AutomationDirect Productivity Suite project: GS30_ModbusRTU (software 4.2.0 (39))
author: Test
Rung notation: left to right = series (deeper-indented lines continue the line above), [a | b] = parallel branches, -- = plain wire, BOX.Pin = further input of the box above; 'quoted' = tag name, ? = field left empty; instruction and field names as stored in the project; options that are off are not listed.

HARDWARE
  Base 1 (1 slots)
    slot 0: P1-550

STRUCTURES
STRUCTURE GS30_Status
  Fault_Code : Uint8, strLength=15
  Warning_Code : Uint8, strLength=15
  Stop : Boolean, strLength=15
  Decel_During_Stop : Boolean, strLength=15
  Standby : Boolean, strLength=15
  Run : Boolean, strLength=15
  JOG_Active : Boolean, strLength=15
  Forward : Boolean, strLength=15
  Transition_Rev_To_FWD : Boolean, strLength=15
  Transition_FWD_To_REV : Boolean, strLength=15
  Reverse : Boolean, strLength=15
  Main_Freq_From_Comm_Interface : Boolean, strLength=15
  Main_Freq_From_Analog : Boolean, strLength=15
  CMD_Operated_By_Comm_Interface : Boolean, strLength=15
  Params_Have_Been_Locked : Boolean, strLength=15
  Drive_Stopped : Boolean, strLength=15
  Drive_Running : Boolean, strLength=15
  Frequency_Command : Int16, strLength=15
  Output_Frequency : Int16, strLength=15
  Output_Current : Int16, strLength=15
  DC_Bus_Voltage : Int16, strLength=15
  Output_Voltage : Int16, strLength=15
  MultiSpeed_Or_PID_Input_StepNo : Int16, strLength=15
  Max_Output_Torque_N-m : Int16, strLength=15
  Digital_Input_Counter_Value : Int16, strLength=15
  Power_Factor_Angle : Int16, strLength=15
  Output_Torque : Int16, strLength=15
  Actual_Motor_Speed_RPM : Int16, strLength=15
  PG1_Feedback_Count : Int16, strLength=15
  PG2_Pulse_Count : Int16, strLength=15
  Power_Output_kW : Int16, strLength=15
STRUCTURE GS30_Command
  Stop : Boolean, strLength=15
  Run_Forward : Boolean, strLength=15
  Run_Reverse : Boolean, strLength=15
  JOG_Forward : Boolean, strLength=15
  JOG_Reverse : Boolean, strLength=15
  Frequency_Command : Uint16, strLength=15
  JOG_Frequency : Array of Uint16, dimensions=1, strLength=15

TAGS  (name : type @system ID = initial value)
  GS30_Modbus_Read : Array[16] of Uint16 @AR1US16-000004
  GS30_Modbus_Write : Array[3] of Int16 @AR1S16-000002
  GS30_ExtendedStatus : Array[8] of Uint16 @AR1US16-000001
  GS30_Status : GS30_Status @USTRUC-000001
  ExpDataInput : Array[6] of Uint8 @AR1US8-000001
  ExpDataInput2 : Array[1] of Uint16 @AR1US16-000003
  'Exp Set' : Boolean @C-000062
  'Exp Get' : Boolean @C-000073
  Enable_GS30_Com : Boolean @C-000079
  TwoBytes : Array[2] of Uint8 @AR1US8-000002
  GS30_IP_Address : String(15) @STR-000024
  GS30_Command : GS30_Command @USTRUC-000003
  Blank_IP : Boolean @C-000085
  GS30_IP_Address_Length : Uint16 @US16-000004

SYSTEM TAGS USED OR MAPPED TO MODBUS
  GS_MBRead : MRX @SSTRUC-000006  // System Structure for Modbus Read
  GS_MBWrite : MWX @SSTRUC-000007  // System Structure for Modbus Write

TASK Main  (Run Every Scan)
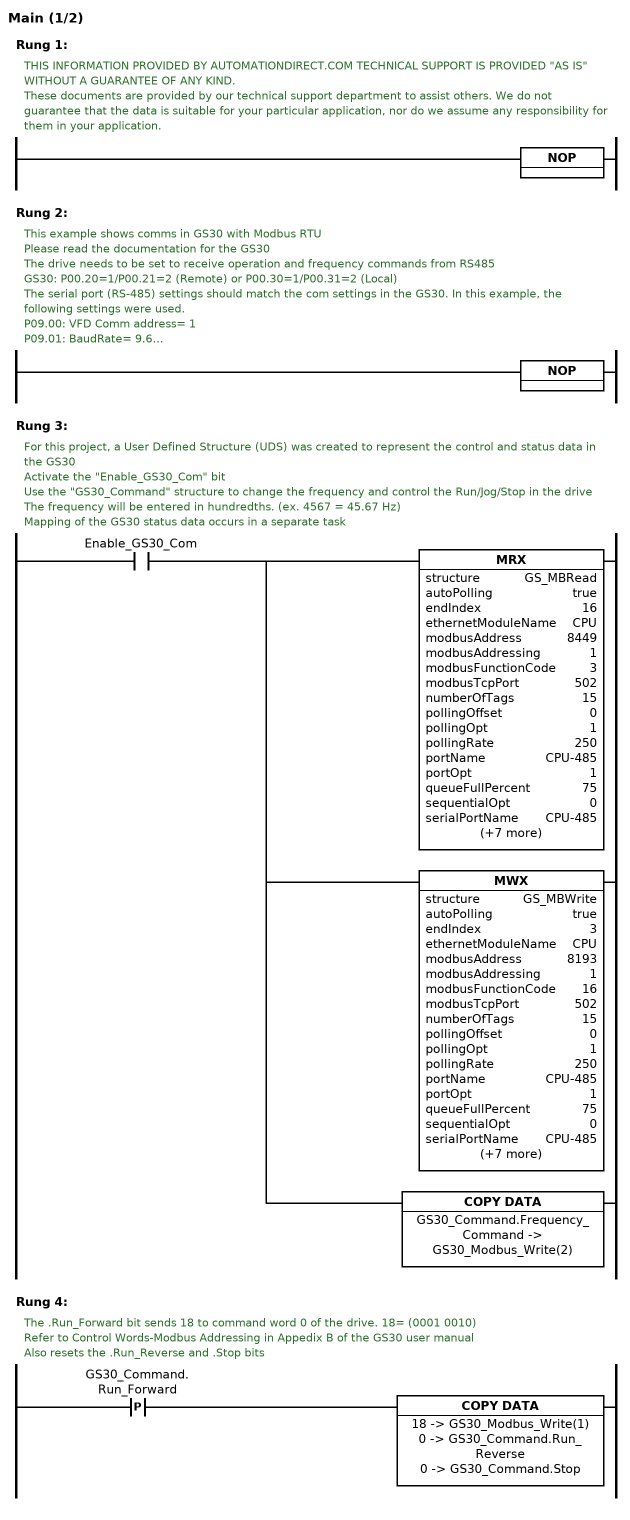
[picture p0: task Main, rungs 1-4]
Rung 1:
  // THIS INFORMATION PROVIDED BY AUTOMATIONDIRECT.COM TECHNICAL SUPPORT IS PROVIDED "AS IS" WITHOUT A GUARANTEE OF ANY KIND.
  // These documents are provided by our technical support department to assist others. We do not guarantee that the data is suitable for your particular application, nor do we assume any responsibility for them in your application.
  NOP()
Rung 2:
  // This example shows comms in GS30 with Modbus RTU
  // Please read the documentation for the GS30
  // The drive needs to be set to receive operation and frequency commands from RS485
  // GS30: P00.20=1/P00.21=2 (Remote) or P00.30=1/P00.31=2 (Local)
  // The serial port (RS-485) settings should match the com settings in the GS30. In this example, the following settings were used.
  // P09.00: VFD Comm address= 1
  // P09.01: BaudRate= 9.6k
  // P09.04: Modbus Protocol= 12: (8 data bits, No parity, 1 stop bit) for RTU
  NOP()
Rung 3:
  // For this project, a User Defined Structure (UDS) was created to represent the control and status data in the GS30
  // Activate the "Enable_GS30_Com" bit
  // Use the "GS30_Command" structure to change the frequency and control the Run/Jog/Stop in the drive
  // The frequency will be entered in hundredths. (ex. 4567 = 45.67 Hz)
  // Mapping of the GS30 status data occurs in a separate task
  NO(Enable_GS30_Com)
    [ MRX(structure=GS_MBRead, autoPolling, endIndex=16, ethernetModuleName=CPU, modbusAddress=8449, modbusAddressing=1, modbusFunctionCode=3, modbusTcpPort=502, numberOfTags=15, pollingOffset=0, pollingOpt=1, pollingRate=250, portName=CPU-485, portOpt=1, queueFullPercent=75, sequentialOpt=0, serialPortName=CPU-485, slaveEthernetNodeNum=255, slaveIpAddress=192.168.1.6, slaveSerialNodeNum=1, startTag=GS30_Modbus_Read, startingIndex=1, stringLength=2, wordSwap)
    | MWX(structure=GS_MBWrite, autoPolling, endIndex=3, ethernetModuleName=CPU, modbusAddress=8193, modbusAddressing=1, modbusFunctionCode=16, modbusTcpPort=502, numberOfTags=15, pollingOffset=0, pollingOpt=1, pollingRate=250, portName=CPU-485, portOpt=1, queueFullPercent=75, sequentialOpt=0, serialPortName=CPU-485, slaveEthernetNodeNum=255, slaveIpAddress=192.168.1.6, slaveSerialNodeNum=1, startTag=GS30_Modbus_Write, startingIndex=1, stringLength=2, wordSwap)
    | CPY(GS30_Command.Frequency_Command -> GS30_Modbus_Write(2)) ]
Rung 4:
  // The .Run_Forward bit sends 18 to command word 0 of the drive. 18= (0001 0010)
  // Refer to Control Words-Modbus Addressing in Appedix B of the GS30 user manual
  // Also resets the .Run_Reverse and .Stop bits
  NOE(GS30_Command.Run_Forward, rising)
    CPY(18 -> GS30_Modbus_Write(1), 0 -> GS30_Command.Run_Reverse, 0 -> GS30_Command.Stop)
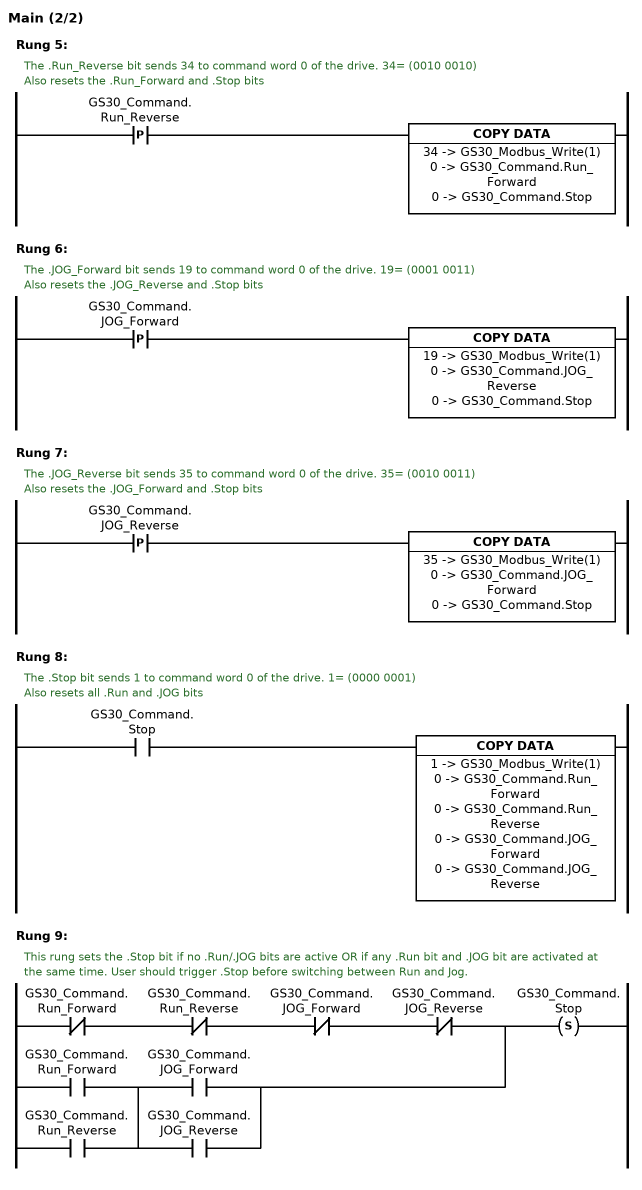
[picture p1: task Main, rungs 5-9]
Rung 5:
  // The .Run_Reverse bit sends 34 to command word 0 of the drive. 34= (0010 0010)
  // Also resets the .Run_Forward and .Stop bits
  NOE(GS30_Command.Run_Reverse, rising)
    CPY(34 -> GS30_Modbus_Write(1), 0 -> GS30_Command.Run_Forward, 0 -> GS30_Command.Stop)
Rung 6:
  // The .JOG_Forward bit sends 19 to command word 0 of the drive. 19= (0001 0011)
  // Also resets the .JOG_Reverse and .Stop bits
  NOE(GS30_Command.JOG_Forward, rising)
    CPY(19 -> GS30_Modbus_Write(1), 0 -> GS30_Command.JOG_Reverse, 0 -> GS30_Command.Stop)
Rung 7:
  // The .JOG_Reverse bit sends 35 to command word 0 of the drive. 35= (0010 0011)
  // Also resets the .JOG_Forward and .Stop bits
  NOE(GS30_Command.JOG_Reverse, rising)
    CPY(35 -> GS30_Modbus_Write(1), 0 -> GS30_Command.JOG_Forward, 0 -> GS30_Command.Stop)
Rung 8:
  // The .Stop bit sends 1 to command word 0 of the drive. 1= (0000 0001)
  // Also resets all .Run and .JOG bits
  NO(GS30_Command.Stop)
    CPY(1 -> GS30_Modbus_Write(1), 0 -> GS30_Command.Run_Forward, 0 -> GS30_Command.Run_Reverse, 0 -> GS30_Command.JOG_Forward, 0 -> GS30_Command.JOG_Reverse)
Rung 9:
  // This rung sets the .Stop bit if no .Run/.JOG bits are active OR if any .Run bit and .JOG bit are activated at the same time. User should trigger .Stop before switching between Run and Jog.
  [ NC(GS30_Command.Run_Forward) NC(GS30_Command.Run_Reverse) NC(GS30_Command.JOG_Forward)
      NC(GS30_Command.JOG_Reverse)
    | [NO(GS30_Command.Run_Forward) | NO(GS30_Command.Run_Reverse)]
      [NO(GS30_Command.JOG_Forward) | NO(GS30_Command.JOG_Reverse)] ]
    SET(GS30_Command.Stop)

TASK GS30_Status_Mapping  (Run Every Scan)
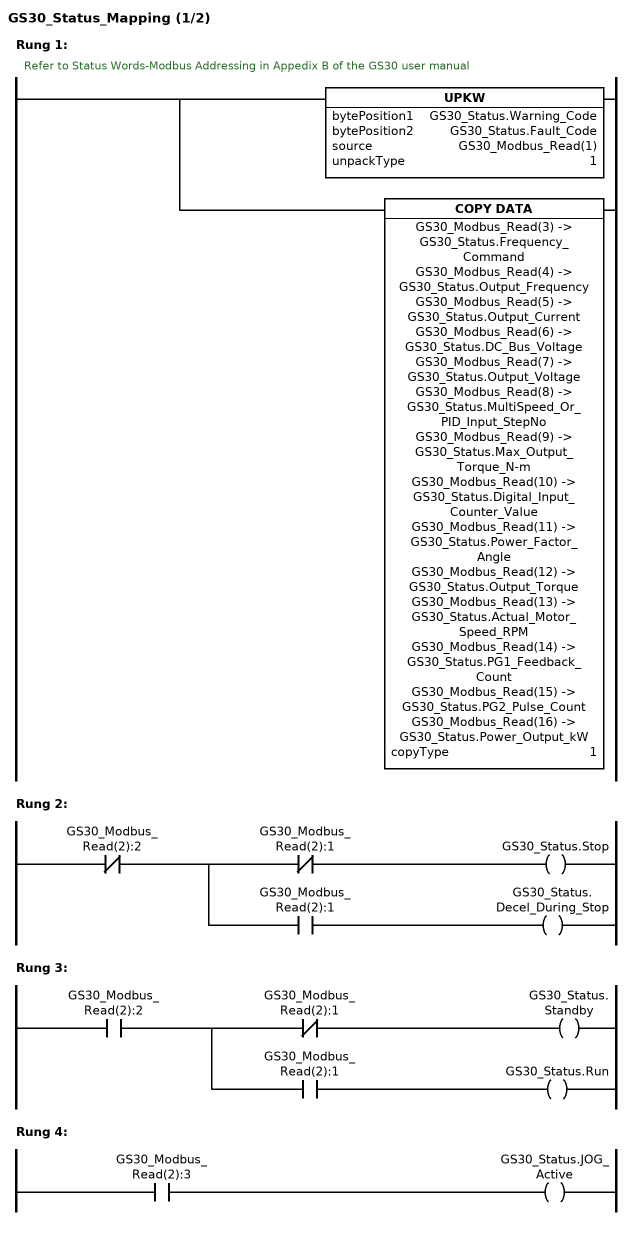
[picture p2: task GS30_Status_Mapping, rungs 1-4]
Rung 1:
  // Refer to Status Words-Modbus Addressing in Appedix B of the GS30 user manual
  UPKW(bytePosition1=GS30_Status.Warning_Code, bytePosition2=GS30_Status.Fault_Code, source=GS30_Modbus_Read(1), unpackType=1)
  CPY(GS30_Modbus_Read(3) -> GS30_Status.Frequency_Command, GS30_Modbus_Read(4) -> GS30_Status.Output_Frequency, GS30_Modbus_Read(5) -> GS30_Status.Output_Current, GS30_Modbus_Read(6) -> GS30_Status.DC_Bus_Voltage, GS30_Modbus_Read(7) -> GS30_Status.Output_Voltage, GS30_Modbus_Read(8) -> GS30_Status.MultiSpeed_Or_PID_Input_StepNo, GS30_Modbus_Read(9) -> GS30_Status.Max_Output_Torque_N-m, GS30_Modbus_Read(10) -> GS30_Status.Digital_Input_Counter_Value, GS30_Modbus_Read(11) -> GS30_Status.Power_Factor_Angle, GS30_Modbus_Read(12) -> GS30_Status.Output_Torque, GS30_Modbus_Read(13) -> GS30_Status.Actual_Motor_Speed_RPM, GS30_Modbus_Read(14) -> GS30_Status.PG1_Feedback_Count, GS30_Modbus_Read(15) -> GS30_Status.PG2_Pulse_Count, GS30_Modbus_Read(16) -> GS30_Status.Power_Output_kW, copyType=1)
Rung 2:
  NC(GS30_Modbus_Read(2):2)
    [NC(GS30_Modbus_Read(2):1) OUT(GS30_Status.Stop) | NO(GS30_Modbus_Read(2):1) OUT(GS30_Status.Decel_During_Stop)]
Rung 3:
  NO(GS30_Modbus_Read(2):2)
    [NC(GS30_Modbus_Read(2):1) OUT(GS30_Status.Standby) | NO(GS30_Modbus_Read(2):1) OUT(GS30_Status.Run)]
Rung 4:
  NO(GS30_Modbus_Read(2):3) OUT(GS30_Status.JOG_Active)
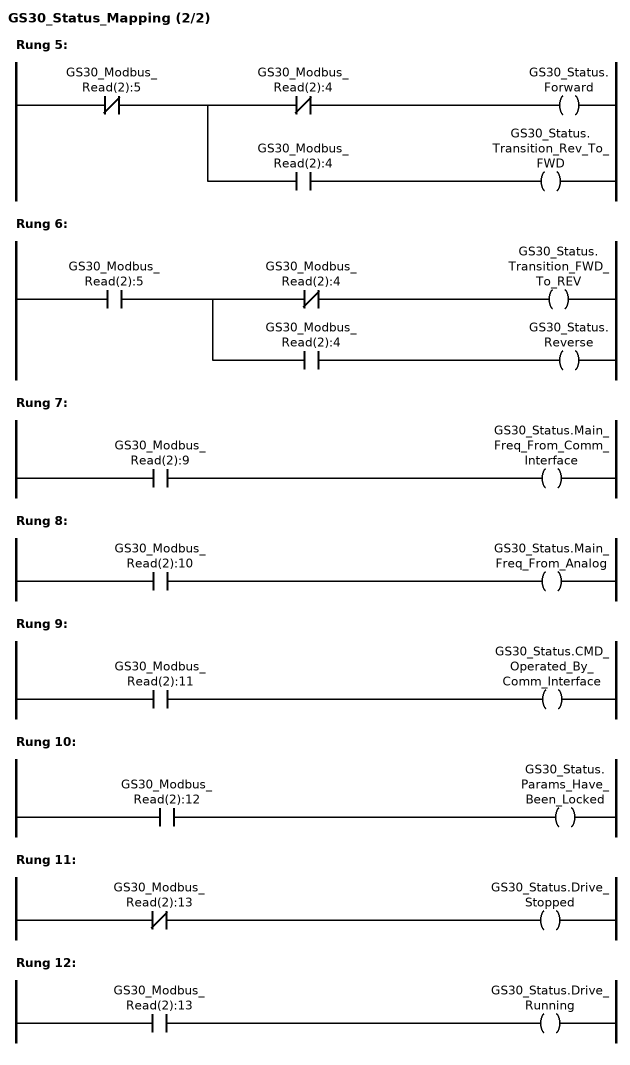
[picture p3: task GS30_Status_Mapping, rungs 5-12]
Rung 5:
  NC(GS30_Modbus_Read(2):5)
    [ NC(GS30_Modbus_Read(2):4) OUT(GS30_Status.Forward)
    | NO(GS30_Modbus_Read(2):4) OUT(GS30_Status.Transition_Rev_To_FWD) ]
Rung 6:
  NO(GS30_Modbus_Read(2):5)
    [ NC(GS30_Modbus_Read(2):4) OUT(GS30_Status.Transition_FWD_To_REV)
    | NO(GS30_Modbus_Read(2):4) OUT(GS30_Status.Reverse) ]
Rung 7:
  NO(GS30_Modbus_Read(2):9) OUT(GS30_Status.Main_Freq_From_Comm_Interface)
Rung 8:
  NO(GS30_Modbus_Read(2):10) OUT(GS30_Status.Main_Freq_From_Analog)
Rung 9:
  NO(GS30_Modbus_Read(2):11) OUT(GS30_Status.CMD_Operated_By_Comm_Interface)
Rung 10:
  NO(GS30_Modbus_Read(2):12) OUT(GS30_Status.Params_Have_Been_Locked)
Rung 11:
  NC(GS30_Modbus_Read(2):13) OUT(GS30_Status.Drive_Stopped)
Rung 12:
  NO(GS30_Modbus_Read(2):13) OUT(GS30_Status.Drive_Running)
